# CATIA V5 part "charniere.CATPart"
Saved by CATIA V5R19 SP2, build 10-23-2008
Part number: charniere
Bounding box of the stored display mesh (mm): x -33.5 to 33.5, y -49.74 to 45.999, z -15.996 to 15.996
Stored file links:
  D:\thinkmotion-MPB\Dropbox\CIAO82010_JCF\SAINT-AIME\0558-SaintAime\CAO2\CAO\charniere.CATPart
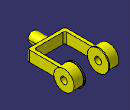
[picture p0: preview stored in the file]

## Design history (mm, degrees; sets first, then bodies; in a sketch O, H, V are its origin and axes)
Set1
  Plane1: type Offset, RefPlane yz-plane, Offset 25.5
Body1 (main body)
  Sketch1 on xy-plane, origin (0, 0, 0), H (1, 0, 0), V (0, 1, 0)
    line L1 (-28, 30) -> (-23, 30)
    line L2 (-23, 30) -> (-23, -25)
    line L3 (-28, 30) -> (-28, -30)
    line L4 (-28, -30) -> (28, -30)
    line L5 (28, -30) -> (28, 30)
    point P6 (28, 30)
    line L6 (28, 30) -> (23, 30)
    line L7 (23, 30) -> (23, -25)
    line L8 (23, -25) -> (-23, -25)
    distance V L2 = 23
    distance L8 L4 = 5
    distance L5 L7 = 5
    distance L6 L4 = 60
    horizontal: L1 H, L4 H, L6 H, L8 H
    vertical: L2 V, L3 V, L5 V, L7 V
    coincidence: P6 L1
    symmetry: L3 L5 V, L1 L4 H, L2 L7 V
  Pad1: profile Sketch1, direction (0, 0, 1), length 8, mirrored extent
  Fillet1: radius 3, on edge [face of Pad1 from Sketch1.L4 | face of Pad1 from Sketch1.L3]; edge [face of Pad1 from Sketch1.L2 | face of Pad1 from Sketch1.L8]; edge [face of Pad1 from Sketch1.L5 | face of Pad1 from Sketch1.L4]; edge [face of Pad1 from Sketch1.L8 | face of Pad1 from Sketch1.L7]
  Sketch2 on face of Pad1 from Sketch1.L4, origin (0, -30, 0), H (1, 0, 0), V (0, 0, 1)
    circle A1 centre (0, 0) radius 7.5
    radius A1 = 7.5
  Pad2: profile Sketch2, direction (0, -1, 0), length 19.74
  Sketch3 on xy-plane, origin (0, 0, 0), H (1, 0, 0), V (0, 1, 0)
    line L1 (-33.5, 30) -> (-33.5, 15)
    line L2 (-33.5, 15) -> (-19, 15)
    line L3 (-19, 15) -> (-19, 14)
    line L4 (-19, 14) -> (-17.5, 14)
    line L5 (-17.5, 14) -> (-17.5, 30)
    line L6 (-17.5, 30) -> (-33.5, 30)
    point P7 (17.5, 30)
    line L7 (17.5, 30) -> (17.5, 14)
    point P8 (17.5, 14)
    line L8 (17.5, 14) -> (19, 14)
    line L9 (19, 14) -> (19, 15)
    point P10 (19, 15)
    line L10 (19, 15) -> (33.5, 15)
    line L11 (33.5, 15) -> (33.5, 30)
    point P12 (33.5, 30)
    line L12 (33.5, 30) -> (17.5, 30)
    reference projected line E1 (-23, 30) -> (-28, 30) from edge [face of Pad1 from Sketch1.L1 | end face of Pad1]
    reference projected line E2 (-23, -25) -> (-23, 30) from edge [face of Pad1 from Sketch1.L2 | end face of Pad1]
    distance L7 L11 = 16
    distance L2 L6 = 15
    distance L5 E2 = 5.5
    distance L4 L6 = 16
    distance L3 L5 = 1.5
    vertical: L1 V, L3 V, L5 V, L7 V, L9 V, L11 V
    horizontal: L2 H, L4 H, L6 H, L8 H, L10 H, L12 H
    coincidence: P7 L6, P8 L4, P10 L2, P12 L6, L6 E1
    symmetry: L1 L11 V, L5 L7 V, L9 L3 V
  Shaft1: profile Sketch3, axis Sketch3.L12, angle 360
  Sketch4 on face of Shaft1 from Sketch3.L1, origin (-33.5, 0, 0), H (0, -1, 0), V (0, 0, 1)
    circle A1 centre (-30, 0) radius 5
    point P1 (-30, 0)
    reference projected circle E1 centre (-30, 0) radius 15 from edge [face of Shaft1 from Sketch3.L2 | face of Shaft1 from Sketch3.L1]
    radius A1 = 5
    coincidence: P1 H
    concentricity: A1 E1
  Pocket1: profile Sketch4, direction (1, 0, 0), through (limit type 3)
  Sketch5 on Plane1, origin (25.5, 0, 0), H (0, 1, 0), V (0, 0, 1)
    circle A1 centre (30, 0) radius 10
    point P1 (30, 0)
    reference projected line E1 (30, -5) -> (30, 5) from edge [face of Pad1 from Sketch1.L6 | face of Pad1 from Sketch1.L5]
    radius A1 = 10
    coincidence: P1 H, P1 E1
